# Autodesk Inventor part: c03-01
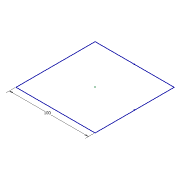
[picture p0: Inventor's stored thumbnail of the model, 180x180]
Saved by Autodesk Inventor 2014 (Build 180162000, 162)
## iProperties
Created: 2011-11
Part Number: c03-01
Material: Generic
Document SubType Name: Modeling
Designer: Thom Tremblay
Density: 1 g/cm^3
Appearance: Generic
Author: Thom Tremblay
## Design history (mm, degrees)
sketch "Sketch1"
  geometry: L1 (50, -50)-(-50, -50); L2 (-50, -50)-(-50, 50); L3 (-50, 50)-(50, 50); L4 (50, 50)-(50, -50); 3 further points
  constraints: 8 end point, 2 midpoint, 2 parallel, 2 perpendicular, 1 horizontal, 1 horizontal alignment, 1 vertical alignment
  dimensions: "d0" = 100 dimension on point (0, 0) L1.start L2.end L1.end L3.end L1 L2 L3 L4 point (-50, 0) point (0, -50); "d0" = 100 distance of L2.end L3.end
